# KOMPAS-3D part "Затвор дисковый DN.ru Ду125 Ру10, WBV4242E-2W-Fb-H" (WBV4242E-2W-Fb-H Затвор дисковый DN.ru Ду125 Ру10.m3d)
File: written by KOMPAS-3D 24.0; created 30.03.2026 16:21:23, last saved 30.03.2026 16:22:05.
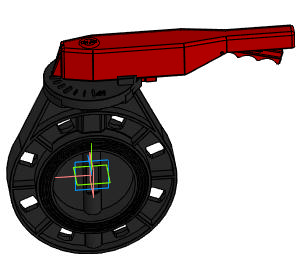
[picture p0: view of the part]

Document properties: Автор: R2D2; Полное имя файла: E:\Работа\Зайцев\WBV4242E-2W-Fb-H Затвор дисковый DN.ru Ду50-200 Ру10\DN125\WBV4242E-2W-Fb-H Затвор дисковый DN.ru Ду125 Ру10.m3d

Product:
- Part/product: Затвор дисковый DN.ru Ду125 Ру10  | designation WBV4242E-2W-Fb-H
    Масса: 4.31
    Раздел спецификации: Прочие изделия
    Примечание: D050-81201

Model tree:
1. Операция без истории:1

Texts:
  WBV4242E-2W-Fb-H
